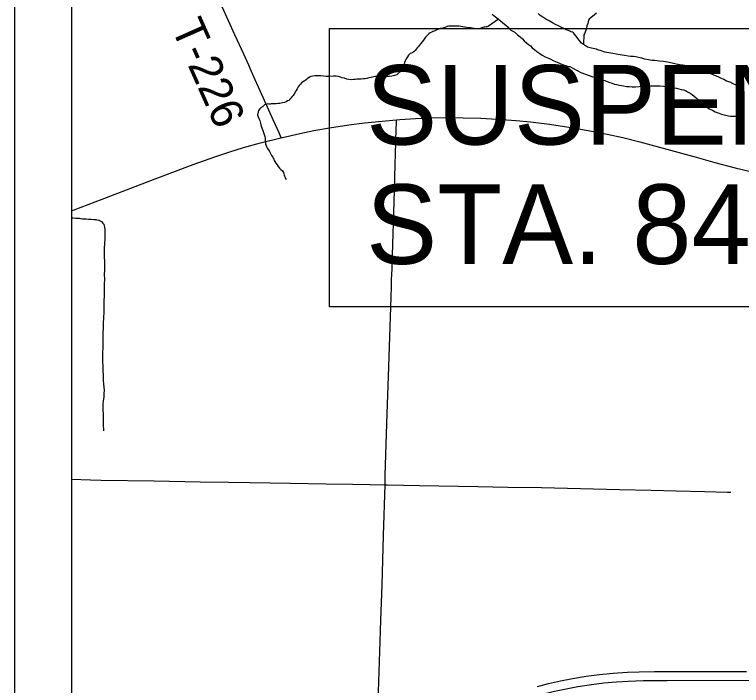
# Model space of a CAD drawing. Extents: x 0 to 64.8, y -5 to 22.
# Drawn here: x 2 to 3.279, y 17.005 to 18.186 of the extents above; entities that cross this region are included whole.
import ezdxf

# ---------------------------------------------------------------- set-up
doc = ezdxf.new("R2010")
doc.units = 0
for name, color, linetype in [('GM_X_Adjacent_County', 7, 'Continuous'), ('GM_X_County', 7, 'Continuous'), ('GM_X_County_Road', 7, 'Continuous'), ('GM_X_Major_River', 7, 'Continuous'), ('GM_X_Minor_River', 7, 'Continuous'), ('GM_X_Township', 7, 'Continuous'), ('GM_X_Township_Road', 7, 'Continuous'), ('GM_X_Township_Road_Text', 7, 'Continuous'), ('GM_X_US_Route', 7, 'Continuous'), ('SH_Data', 7, 'Continuous'), ('SH_Masking', 7, 'Continuous'), ('SH_Text', 7, 'Continuous')]:
    doc.layers.add(name, color=color, linetype=linetype)

msp = doc.modelspace()

# ---------------------------------------------------------------- linework, layer by layer
at = {"layer": 'GM_X_Adjacent_County'}
msp.add_lwpolyline([(2.1, 19.9176), (2.1, 14.1), (8.9, 14.1), (8.9, 19.781)], dxfattribs=at)
at = {"layer": 'GM_X_County'}
msp.add_lwpolyline([(2.1, 19.9176), (2.1, 14.1), (8.9, 14.1), (8.9, 19.781)], dxfattribs=at)
at = {"layer": 'GM_X_County_Road'}
for points in [[(2.672, 18.0006), (2.6775, 18.0011), (2.7055, 18.0028), (2.7303, 18.0038), (2.7614, 18.0044), (2.7894, 18.0041), (2.8205, 18.0033), (2.8485, 18.0018), (2.8826, 17.9994), (2.9074, 17.9971), (2.9413, 17.9929), (2.9752, 17.9878), (3.0089, 17.982), (3.0425, 17.9753), (3.0698, 17.9692), (3.0999, 17.9616), (3.154, 17.9471), (3.199, 17.9348), (3.2318, 17.9255), (3.2679, 17.9162), (3.2921, 17.9105), (3.3024, 17.9084)], [(2.4693, 17.9691), (2.5021, 17.9767), (2.5264, 17.9817), (2.554, 17.9865), (2.5878, 17.9917), (2.6156, 17.9953), (2.6465, 17.9985), (2.672, 18.0006)], [(2.6518, 17.3585), (2.6522, 17.3748), (2.6556, 17.4835), (2.658, 17.5487), (2.6623, 17.6885), (2.6629, 17.7071), (2.6633, 17.7194), (2.6637, 17.7287), (2.664, 17.738), (2.6647, 17.7628), (2.6676, 17.8559), (2.6696, 17.9212), (2.6709, 17.9615), (2.6715, 17.9864), (2.6717, 17.9926), (2.672, 18.0006)], [(2.1, 17.8404), (2.105, 17.8422), (2.1543, 17.8612), (2.2472, 17.8966), (2.3141, 17.9219), (2.3522, 17.9355), (2.3787, 17.9443), (2.4026, 17.9516), (2.4325, 17.9599), (2.4687, 17.969), (2.4693, 17.9691)], [(2.6393, 16.9658), (2.6397, 16.9772), (2.6432, 17.0828), (2.6443, 17.1201), (2.6464, 17.1822), (2.6492, 17.2692), (2.6518, 17.3585)]]:
    msp.add_lwpolyline(points, dxfattribs=at)
at = {"layer": 'GM_X_Major_River'}
for points in [[(2.8401, 18.1864), (2.8458, 18.1821), (2.8506, 18.1785), (2.8551, 18.1746), (2.8592, 18.1711), (2.8641, 18.1672), (2.8686, 18.1637), (2.873, 18.1586), (2.8798, 18.1547), (2.885, 18.1504), (2.8895, 18.1468), (2.8933, 18.1433), (2.8966, 18.1398), (2.9004, 18.1363), (2.9041, 18.1332), (2.9075, 18.1305), (2.9108, 18.1274), (2.9149, 18.1242), (2.9187, 18.1211), (2.9239, 18.1175), (2.9281, 18.1144), (2.9337, 18.1112), (2.939, 18.1088), (2.9431, 18.1072), (2.9477, 18.1048), (2.9529, 18.1024), (2.9575, 18.1008), (2.9612, 18.0992), (2.9658, 18.0972), (2.9699, 18.096), (2.9733, 18.0947), (2.9768, 18.0943), (2.9962, 18.0839)], [(2.9974, 18.1357), (2.9834, 18.1538), (2.9816, 18.1546), (2.9793, 18.1554), (2.977, 18.1563), (2.9744, 18.1575), (2.9702, 18.1591), (2.9661, 18.1615), (2.9612, 18.1638), (2.9567, 18.1662), (2.9518, 18.1686), (2.9461, 18.1714), (2.9405, 18.1746), (2.9348, 18.1778), (2.9292, 18.1813), (2.9247, 18.1844), (2.9209, 18.1876)], [(3.2805, 18.0562), (3.2749, 18.059), (3.2696, 18.0614), (3.2639, 18.0638), (3.2591, 18.0666), (3.2526, 18.0686), (3.2478, 18.0714), (3.2425, 18.0738), (3.2376, 18.0762), (3.2331, 18.0782), (3.2289, 18.0798), (3.2248, 18.0814), (3.2206, 18.083), (3.2165, 18.0846), (3.212, 18.0866), (3.2082, 18.0878), (3.2037, 18.0895), (3.1973, 18.0911), (3.1927, 18.0927), (3.1878, 18.094), (3.1833, 18.0952), (3.1791, 18.0961), (3.1749, 18.0966), (3.1696, 18.0974), (3.164, 18.0987), (3.1568, 18.1), (3.1488, 18.1021), (3.1416, 18.1034), (3.1344, 18.1039), (3.1303, 18.1044), (3.1265, 18.1049), (3.1211, 18.105), (3.1151, 18.1059), (3.109, 18.1075), (3.1034, 18.1088), (3.0977, 18.1101), (3.0928, 18.1113), (3.0886, 18.1122), (3.084, 18.1123), (3.0795, 18.1128), (3.0731, 18.1137), (3.0689, 18.1141), (3.0651, 18.115), (3.0522, 18.1172), (3.0454, 18.1185), (3.0386, 18.1197), (3.0318, 18.1218), (3.0261, 18.1238), (3.0235, 18.125), (3.0208, 18.1255), (3.0152, 18.1264), (3.008, 18.1284), (2.9974, 18.1357)], [(2.9962, 18.0839), (3.0171, 18.0765)], [(3.0171, 18.0765), (3.0205, 18.0749), (3.0246, 18.0737), (3.0292, 18.0721), (3.0337, 18.0708), (3.0382, 18.0696), (3.0427, 18.068), (3.0469, 18.0664), (3.051, 18.0648), (3.0552, 18.0635), (3.0594, 18.0627), (3.0643, 18.0614), (3.0711, 18.0601), (3.0764, 18.0593), (3.0813, 18.0591), (3.0863, 18.0586), (3.0924, 18.0589), (3.0985, 18.0595), (3.1042, 18.0601), (3.1091, 18.0604), (3.1144, 18.0607), (3.1198, 18.0606), (3.1262, 18.0604), (3.135, 18.0602), (3.1414, 18.0597), (3.1471, 18.0588), (3.152, 18.0579), (3.1558, 18.0575), (3.16, 18.057), (3.1642, 18.0561), (3.1683, 18.0553), (3.1728, 18.054), (3.1766, 18.0532), (3.18, 18.052), (3.1838, 18.05), (3.1883, 18.0472), (3.192, 18.0449), (3.1954, 18.0425), (3.1988, 18.0394), (3.2017, 18.0363), (3.204, 18.034), (3.2073, 18.0316), (3.2115, 18.0292), (3.2156, 18.0257), (3.2189, 18.0222), (3.2219, 18.0199), (3.2275, 18.0175), (3.2324, 18.0147), (3.2377, 18.0127), (3.2434, 18.0107), (3.2558, 18.0077), (3.2596, 18.0073), (3.2638, 18.0072), (3.2672, 18.0071), (3.271, 18.007), (3.2752, 18.0065), (3.2817, 18.006)]]:
    msp.add_lwpolyline(points, dxfattribs=at)
at = {"layer": 'GM_X_Minor_River'}
for points in [[(3.0238, 18.1881), (3.0199, 18.1855), (3.0106, 18.1777), (3.0098, 18.1759), (3.009, 18.1728), (3.0082, 18.1698), (3.0069, 18.1657), (3.0061, 18.1615), (3.0049, 18.1585), (3.004, 18.1547), (3.0028, 18.1521), (3.0016, 18.1502), (3.0006, 18.1335)], [(2.8514, 18.1778), (2.8339, 18.1656), (2.8316, 18.1645), (2.8297, 18.1642), (2.8274, 18.1639), (2.8255, 18.1635), (2.8221, 18.1625), (2.819, 18.1614), (2.8152, 18.1607), (2.8083, 18.1613), (2.8019, 18.1622), (2.7954, 18.1631), (2.7814, 18.1653), (2.7787, 18.1653), (2.7756, 18.1654), (2.7726, 18.1655), (2.7699, 18.1655), (2.7669, 18.1656), (2.7638, 18.1653), (2.7608, 18.1646), (2.7585, 18.1639), (2.755, 18.1625), (2.7512, 18.1614), (2.7489, 18.1611), (2.7466, 18.1604), (2.7431, 18.1589), (2.7381, 18.1568), (2.7358, 18.1561), (2.7339, 18.1546), (2.7312, 18.1535), (2.7288, 18.152), (2.7253, 18.1483), (2.723, 18.1461), (2.7206, 18.1423), (2.7179, 18.1386), (2.7144, 18.1345), (2.7124, 18.1319), (2.71, 18.1293), (2.7085, 18.127), (2.7065, 18.1248), (2.7049, 18.1225), (2.7026, 18.1203), (2.7007, 18.1192), (2.698, 18.1181), (2.6957, 18.1171), (2.6929, 18.1145), (2.6882, 18.1066), (2.6874, 18.1043), (2.6862, 18.1013), (2.6853, 18.0987), (2.6849, 18.0968), (2.6837, 18.0934), (2.6825, 18.0904), (2.6805, 18.0877), (2.6786, 18.0851), (2.6766, 18.0836), (2.6747, 18.0822), (2.6727, 18.0799), (2.6681, 18.0785), (2.6635, 18.0775), (2.6589, 18.0768), (2.654, 18.0762), (2.6501, 18.0759), (2.646, 18.076), (2.6425, 18.0764), (2.6399, 18.0769), (2.6372, 18.0769), (2.6342, 18.0766), (2.6322, 18.0763), (2.6296, 18.0756), (2.6265, 18.0749), (2.6231, 18.0742), (2.62, 18.0735), (2.6165, 18.0729), (2.6131, 18.0726), (2.6097, 18.0722), (2.6059, 18.072), (2.6024, 18.072), (2.5994, 18.0717), (2.5959, 18.0714), (2.5925, 18.0711), (2.5879, 18.0716), (2.5845, 18.0724), (2.5804, 18.0737), (2.5762, 18.0745), (2.5732, 18.0757), (2.5698, 18.077), (2.566, 18.0774), (2.561, 18.0772), (2.5549, 18.0769), (2.5484, 18.0771), (2.5435, 18.0776), (2.5389, 18.078), (2.5355, 18.0781), (2.5317, 18.0782), (2.5282, 18.0779), (2.5214, 18.0769), (2.5187, 18.0758), (2.5148, 18.0729), (2.5128, 18.0707), (2.5094, 18.0688)], [(2.5094, 18.0688), (2.5067, 18.067), (2.5047, 18.0655), (2.5031, 18.0633), (2.5008, 18.061), (2.4992, 18.0584), (2.4973, 18.0554), (2.4953, 18.052), (2.4929, 18.0479), (2.4901, 18.0434), (2.4878, 18.0412), (2.4866, 18.0393), (2.4843, 18.0367), (2.4827, 18.0348), (2.4804, 18.0341), (2.4777, 18.0323), (2.475, 18.0312), (2.4711, 18.0302), (2.4689, 18.0298), (2.4669, 18.0295), (2.4639, 18.0292), (2.4601, 18.0289), (2.457, 18.0286), (2.4543, 18.0286), (2.4517, 18.0287), (2.4494, 18.0284), (2.4475, 18.028), (2.4456, 18.0285), (2.4425, 18.0278), (2.4402, 18.0274), (2.4387, 18.0256), (2.4363, 18.0237), (2.434, 18.0223), (2.4313, 18.0197), (2.4289, 18.0167), (2.4276, 18.0091), (2.4287, 18.0057), (2.4301, 18.0018), (2.4312, 17.9991), (2.4326, 17.9949), (2.434, 17.9896), (2.4365, 17.9819), (2.439, 17.975), (2.4405, 17.9712), (2.4408, 17.9677), (2.4407, 17.9655), (2.4407, 17.9632), (2.4414, 17.9601), (2.4417, 17.9571), (2.4424, 17.9552), (2.4446, 17.9509), (2.4468, 17.9475), (2.4483, 17.9451), (2.4497, 17.9424), (2.4519, 17.9378), (2.4541, 17.9351), (2.4552, 17.9332), (2.4559, 17.9313), (2.4567, 17.929), (2.4581, 17.927), (2.4596, 17.9243), (2.4618, 17.9213), (2.4636, 17.9182), (2.4659, 17.9155), (2.4685, 17.9131), (2.4711, 17.9108), (2.4729, 17.9081), (2.4736, 17.9054), (2.4744, 17.9031), (2.4751, 17.9012), (2.4758, 17.8993), (2.4765, 17.8973), (2.478, 17.8954), (2.478, 17.8958), (2.478, 17.8954)], [(2.1, 17.828), (2.1034, 17.8279), (2.1076, 17.8274), (2.111, 17.8274), (2.1141, 17.8273), (2.1167, 17.8269), (2.1197, 17.8264), (2.1228, 17.8263), (2.1258, 17.8263), (2.13, 17.8258), (2.1346, 17.8257), (2.1403, 17.8252), (2.143, 17.8251), (2.1449, 17.8247), (2.1483, 17.8242), (2.1505, 17.823), (2.1532, 17.8215), (2.1554, 17.8188), (2.1569, 17.8168), (2.1576, 17.8141), (2.1583, 17.8115), (2.1586, 17.8077), (2.1589, 17.7905), (2.1584, 17.7829), (2.1578, 17.775), (2.1577, 17.7674), (2.1575, 17.7601), (2.158, 17.7503), (2.1582, 17.743), (2.1585, 17.7358), (2.1579, 17.7286), (2.1581, 17.7202), (2.1579, 17.7119), (2.1577, 17.7024), (2.1575, 17.6917), (2.1572, 17.6815), (2.157, 17.672), (2.1568, 17.6632), (2.1562, 17.6518), (2.156, 17.6435), (2.1558, 17.6343), (2.1556, 17.626), (2.1554, 17.6176), (2.1556, 17.6089), (2.1554, 17.5994), (2.1548, 17.591), (2.155, 17.583), (2.1548, 17.5751), (2.1554, 17.5671), (2.1552, 17.5598), (2.1558, 17.5499), (2.156, 17.5423), (2.1566, 17.5355), (2.1572, 17.5301), (2.1575, 17.5248), (2.1573, 17.5187), (2.1568, 17.5123), (2.1559, 17.5062), (2.1554, 17.5005), (2.1553, 17.4952), (2.1555, 17.4899), (2.1558, 17.4834), (2.1561, 17.4792), (2.156, 17.4743), (2.1558, 17.4693), (2.1557, 17.4652), (2.156, 17.461), (2.1563, 17.4575), (2.1567, 17.4552), (2.1566, 17.4533)]]:
    msp.add_lwpolyline(points, dxfattribs=at)
at = {"layer": 'GM_X_Township'}
msp.add_lwpolyline([(2.1, 19.9176), (2.1, 14.1), (5.5757, 14.1)], dxfattribs=at)
at = {"layer": 'GM_X_Township_Road'}
for points in [[(2.4693, 17.9691), (2.4654, 17.9778), (2.4552, 18.0004), (2.4476, 18.0175), (2.4373, 18.0401), (2.4232, 18.0712), (2.4146, 18.0911), (2.4121, 18.0967), (2.4031, 18.1163), (2.3878, 18.1503), (2.3428, 18.2494), (2.321, 18.2975), (2.3061, 18.3317), (2.2997, 18.3459), (2.2898, 18.3661)], [(2.1, 17.368), (2.1338, 17.3672), (2.1522, 17.3666), (2.2457, 17.3653), (2.3267, 17.3638), (2.3766, 17.363), (2.414, 17.3625), (2.4856, 17.3614), (2.5479, 17.3602), (2.5947, 17.3594), (2.6258, 17.359), (2.6518, 17.3585)], [(2.6518, 17.3585), (2.6561, 17.3584), (2.7122, 17.3572), (2.8149, 17.3553), (2.8679, 17.3543), (2.9271, 17.3535), (3.0641, 17.3503), (3.1201, 17.3489), (3.1637, 17.3478), (3.2136, 17.3467), (3.254, 17.3452), (3.2602, 17.3452)]]:
    msp.add_lwpolyline(points, dxfattribs=at)
at = {"layer": 'GM_X_US_Route'}
for points in [[(2.9202, 17.0036), (2.9395, 17.0086), (2.9601, 17.0133), (2.9815, 17.0174), (3.0055, 17.0214), (3.0289, 17.0245), (3.0531, 17.0269), (3.0785, 17.0286), (3.099, 17.0294), (3.1258, 17.0298), (3.2874, 17.0298)], [(2.1, 16.7212), (2.4096, 16.822), (2.5235, 16.8592), (2.5975, 16.8835), (2.6372, 16.8963), (2.6584, 16.9032), (2.7218, 16.9236), (2.8783, 16.9748), (2.908, 16.9839), (2.9308, 16.9903), (2.95, 16.995), (2.9701, 16.9994), (2.9908, 17.0032), (3.0148, 17.0069), (3.0369, 17.0097), (3.0586, 17.0117), (3.0796, 17.013), (3.1063, 17.0139), (3.148, 17.0142), (3.3208, 17.0143), (3.6447, 17.0146)]]:
    msp.add_lwpolyline(points, dxfattribs=at)
at = {"layer": 'SH_Data'}
for p, q in [((2, 21), (2, 14)), ((2.1, 20.9), (2.1, 14.1))]:
    msp.add_line(p, q, dxfattribs=at)
at = {"layer": 'SH_Masking'}
msp.add_lwpolyline([(2.5541, 18.1613), (4.6267, 18.1613), (4.6267, 17.6713), (2.5541, 17.6713)], close=True, dxfattribs=at)
at = {"layer": 'SH_Text'}
msp.add_lwpolyline([(2.5541, 18.1613), (4.6267, 18.1613), (4.6267, 17.6713), (2.5541, 17.6713)], close=True, dxfattribs=at)

# ---------------------------------------------------------------- texts
at = {"layer": 'GM_X_Township_Road_Text'}
msp.add_text('T-226', height=0.05682, rotation=293.9629, dxfattribs=at).set_placement((2.2749, 18.163))
at = {"layer": 'SH_Text'}
for s, p in [('SUSPEND PROJECT', (2.6185, 17.957)), ('STA. 848+23.26', (2.6185, 17.747))]:
    msp.add_text(s, height=0.14, dxfattribs=at).set_placement(p)

doc.saveas('drawing.dxf')
